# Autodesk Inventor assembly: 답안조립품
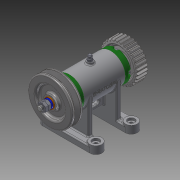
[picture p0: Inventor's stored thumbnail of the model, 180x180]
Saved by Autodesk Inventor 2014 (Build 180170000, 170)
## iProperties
Created: 2015-11
Part Number: 답안조립품
Document SubType Name: Assembly
Designer: basic
Author: basic
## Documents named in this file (16)
- C:\Users\basic\Desktop\451110V1006\답안조립품.iam
- C:\Users\basic\Desktop\451110V1006\본체.ipt
- C:\Users\basic\Desktop\451110V1006\베어링 15 x 32 x 9.ipt
- C:\Users\basic\Desktop\451110V1006\축.ipt
- C:\Users\basic\Desktop\451110V1006\커버.ipt
- C:\Users\basic\Desktop\451110V1006\오일 실 15 25 7.ipt
- C:\Users\basic\Desktop\451110V1006\볼트 M4 x 12.ipt
- C:\Users\basic\Desktop\451110V1006\키 3 x 3 x 12.ipt
- C:\Users\basic\Desktop\451110V1006\V벨트풀리.ipt
- C:\Users\basic\Desktop\451110V1006\스퍼기어.ipt
- C:\Users\basic\Desktop\451110V1006\와셔 8x17.ipt
- C:\Users\basic\Desktop\451110V1006\스프링와셔 8.ipt
- C:\Users\basic\Desktop\451110V1006\볼트 M 6 x 8.ipt
- C:\Users\basic\Desktop\451110V1006\와셔 6x11.5.ipt
- C:\Users\basic\Desktop\451110V1006\니플 M 6 x 0.75.ipt
- C:\Users\basic\Desktop\451110V1006\너트 M 8.ipt
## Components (11 placed, 3 different names)
1. KS B 2023 6002 - 15 x 32 x 9:1
2. KS B 2023 6002 - 15 x 32 x 9:2
3. V벨트풀리:1
4. ISO 4762 M4 x 12:1
5. ISO 4762 M4 x 12:3
6. ISO 4762 M4 x 12:4
7. ISO 4762 M4 x 12:5
8. ISO 4762 M4 x 12:2
9. ISO 4762 M4 x 12:6
10. ISO 4762 M4 x 12:7
11. ISO 4762 M4 x 12:8
